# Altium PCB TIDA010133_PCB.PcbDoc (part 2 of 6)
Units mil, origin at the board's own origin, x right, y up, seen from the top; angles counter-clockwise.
Board outline 4100 x 6400 mil, 8 copper layers (Top Layer, Ground 1, Signal 1, Power 1, Ground 2, Signal 2, Power 2, Bottom Layer), stack 60.4 mil thick; 587 components, 322 nets, 1661 pads, 859 vias.
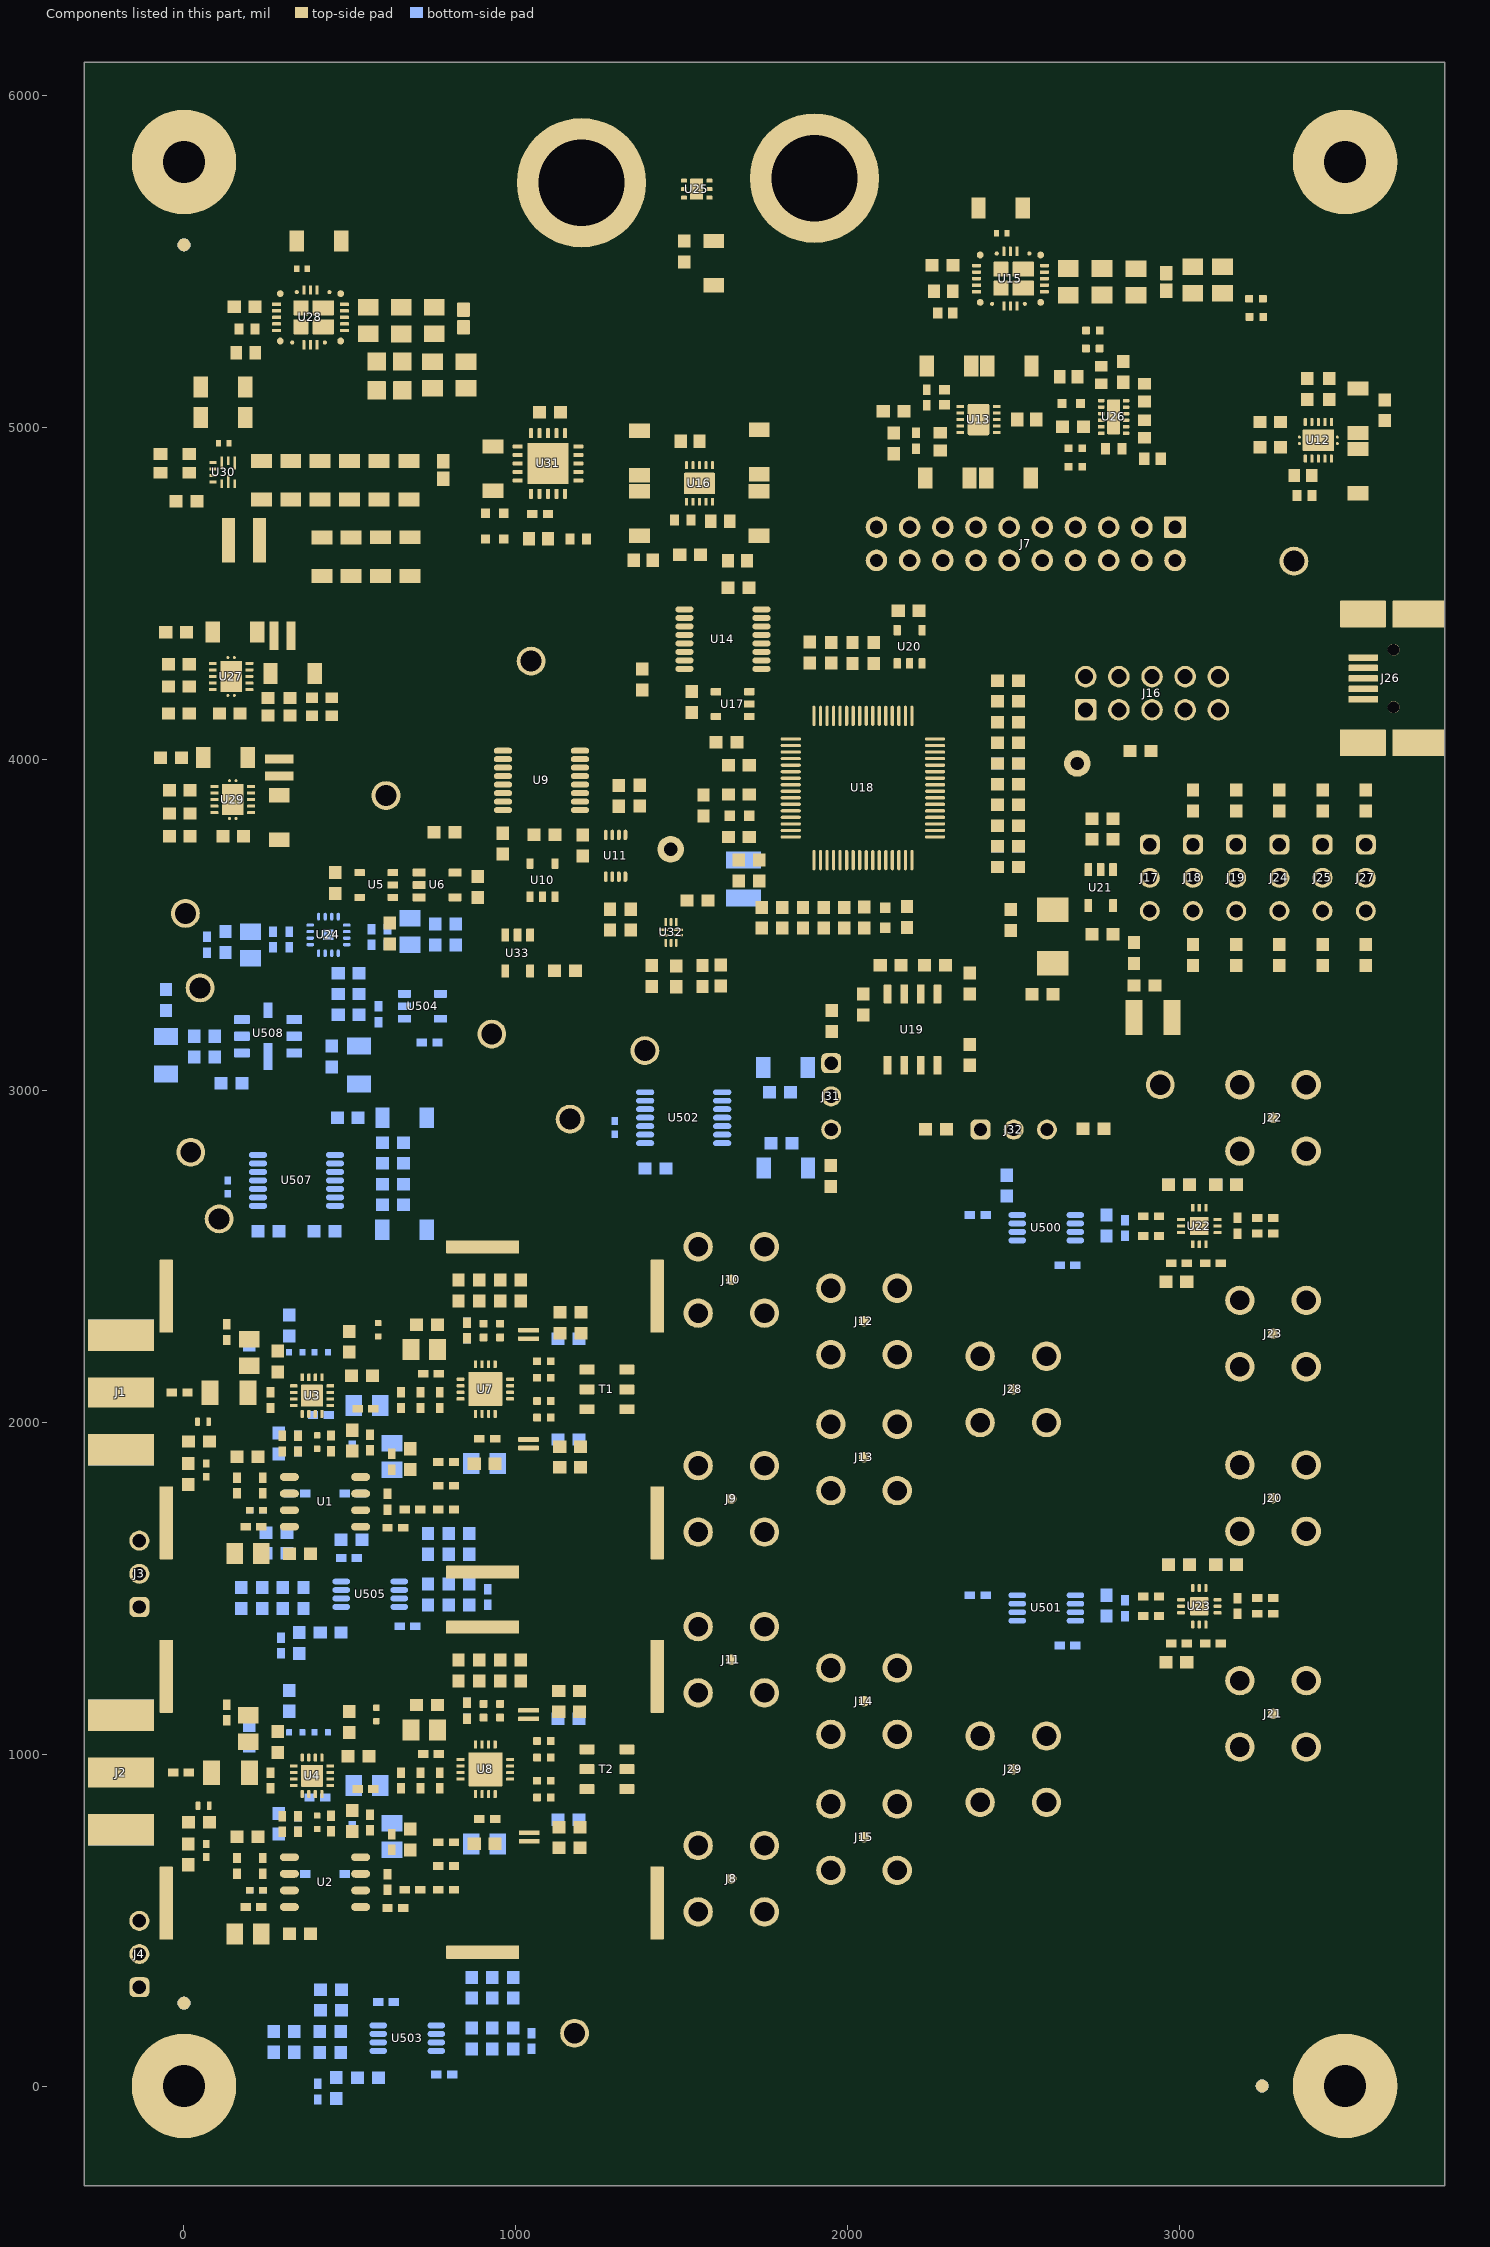
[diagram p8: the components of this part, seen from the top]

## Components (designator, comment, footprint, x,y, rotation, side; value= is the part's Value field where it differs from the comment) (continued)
U15 "TPSM82913RDUR" RDU0028A-MFG 2491.34,5448.25 r90 top locked
U16 "TPS7A3901DSCR" DSC0010J 1554,4831 r270 top locked
U17 "SN74LVC1G125DBVR" DBV0005A_L 1653.82,4165.74 r180 top locked
U18 "FT4232HL" LQFP64_L 2046.73,3912.92 r180 top locked
U19 "93LC46BT-I/SN" SOIC-8 2196.09,3184.32 r270 top locked
U20 "SN74LVC1G125DBVR" DBV0005A_L 2187.48,4338.58 r90 top locked
U21 "TLV70233DBVR" DBV0005A_N 2763.47,3612.45 r270 top locked
U22 "TLV3605RVKR" RVK0012A 3060.66,2592.43 r270 top locked
U23 "TLV3605RVKR" RVK0012A 3060.66,1446.17 r270 top locked
U24 "DAC80508MRTET" RTE0016D 435.51,3470 r90 bottom locked
U25 "TVS1400DRVR" DRV0006A 1545.46,5718.18 r180 top
U26 "LM27762DSSR" DSS0012B 2802.59,5031.38 r180 top
U27 "TPS7A9401DSC" DSC0010J-MFG 142,4249 r0 top
U28 "TPSM82913RDUR" RDU0028A-MFG 381.3,5331.75 r90 top
U29 "TPS7A9401DSC" DSC0010J-MFG 147,3878 r0 top locked
U30 "TPS62913RPUR" RPU0010A-MFG 123.51,4864.69 r90 top locked
U31 "TPS7A3301RGWR" RGW0020A 1097.32,4891.12 r90 top
U32 "TMUX121NKGR" NKG0010A-MFG 1468.15,3477.43 r0 top
U33 "SN74LVC1G126DBVR" DBV0005A_N 1005.78,3415.33 r270 top
U500 "OPA2188AIDGKT" DGK0008A_N 2599.54,2587.32 r180 bottom locked
U501 "OPA2188AIDGKT" DGK0008A_N 2599.53,1441.06 r180 bottom locked
U502 "TPL0102-100PWR" PW0014A_N 1506.25,2919.07 r0 bottom locked
U503 "OPA2188AIDGKT" DGK0008A_N 673.23,144.17 r0 bottom locked
U504 "OPA189IDBVR" DBV0005A_N 719.3,3254.91 r0 bottom locked
U505 "OPA2188AIDGKT" DGK0008A_N 561.4,1482.47 r0 bottom locked
U507 "TPL0102-100PWR" PW0014A_N 339.25,2729.91 r0 bottom locked
U508 "REF7025QFKHR" FKH0008A-MFG 253.34,3164.49 r0 bottom locked
Y1 "ABM3-12.000MHZ-D2Y-T" XTAL_ABM3 2619.41,3465.41 r90 top locked
ZZ1 "These assemblies must be clean and free from flux and all contaminants. Use of no clean flux is not acceptable." AssemblyNote -1237.69,6728.09 r0 top
ZZ2 "These assemblies must comply with workmanship standards IPC-A-610 Class 2, unless otherwise specified." AssemblyNote -1237.69,6639.53 r0 top
ZZ3 "Indication provided for the D* components at their cathode side." AssemblyNote -1237.6,6557.21 r0 top
ZZ4 "This Assembly Note is for PCB labels only" AssemblyNoteLabel -1233.49,6464.16 r0 top
ZZ5 "These assemblies are ESD sensitive, ESD precautions shall be observed." AssemblyNote -1233.49,6355.28 r0 top

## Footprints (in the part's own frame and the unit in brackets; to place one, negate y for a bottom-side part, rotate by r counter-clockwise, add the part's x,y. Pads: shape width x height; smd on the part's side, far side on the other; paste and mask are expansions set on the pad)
0306 [mm] "based on TDK recommendation (similar to Taiyo Yuden and MuRata)"
  rrect29% 0.35x1.6 smd: 1(-0.325,0) 2(0.325,0)
  body extent -0.44,-0.85 0.44,0.85, height 0.6
0402 [mm] "0402 from SM-752 data"
  rect 0.8x0.6 smd: 1(-0.6,0) 2(0.6,0)
  silkscreen extent -1.22,-0.52 1.22,0.52, body extent -0.55,-0.3 0.55,0.3, height 0.6
0402L [mm] "0402 from SM-752 data"
  rect 0.6x0.5 smd: 1(-0.5,0) 2(0.5,0)
  body extent -0.55,-0.3 0.55,0.3, height 0.6
0603 [mm] "0603 from SM-752 data"
  rect 1x0.95 smd: 1(-0.8,0) 2(0.8,0)
  silkscreen extent -1.52,-0.69 1.52,0.69, body extent -0.87,-0.47 0.87,0.47, height 1
0805_HV [mil] "0805 with 30mil clearance between pads"
  rect 50x63 smd: 1(-40,0) 2(40,0)
  silkscreen extent -74,-40 74,40, body extent -43,-29 43,29, height 57
1206 [mm] "1206 from SM-752 data"
  rect 1.3x1.85 smd: 1(-1.45,0) 2(1.45,0)
  silkscreen extent -2.4,-1.21 2.4,1.21, body extent -1.7,-0.9 1.7,0.9, height 1.35
1206_190 [mm] "1206_190"
  rect 1.1x1.6 smd: 1(-1.7,0) 2(1.7,0)
  silkscreen extent -0.9,-1 0.9,1, body extent -1.75,-0.95 1.75,0.95, height 1.9
1210_270 [mm] "1210"
  rect 1.3x2.7 smd: 1(-1.45,0) 2(1.45,0)
  silkscreen extent -2.32,-1.57 2.32,1.57, body extent -1.7,-1.35 1.7,1.35, height 2.7
AssemblyNote [mil] "Assembly Note"
AssemblyNoteLabel [mil] "Assembly Note for PCB Labels"
CAPC1608X87X35NL15T15 [mm] "Chip Capacitor, 2-Leads, Body 1.60x0.80mm, IPC Medium Density"
  rect 0.9x1 smd: 1(-0.675,0) 2(0.675,0)
  body extent -0.87,-0.48 0.87,0.47, height 0.87
CAPC1608X90X35ML10T15 [mm] "Chip Capacitor, 2-Leads, Body 1.60x0.80mm, IPC Low Density"
  rect 0.95x1.05 smd: 1(-0.725,0) 2(0.725,0)
  body extent -0.85,-0.45 0.85,0.45, height 0.9
CE_Mark_5mm [mil] "Minimum text height for CE Mark"
  silkscreen extent -138,-98 138,98
CONN_LTI_SASF546-P26-X1 [mm]
  round 0.8 smd: 1(0,0)
  round 2.25 hole 1.5: 2(-2.54,2.54) 3(-2.54,-2.54) 4(2.54,-2.54) 5(2.54,2.54)
  silkscreen extent -3.4,-3.4 3.4,3.4, body extent -3.17,-3.17 3.17,3.17, height 12.53
D0008A_N [mm] "SOIC, 8-Leads, Body 4.9x3.9mm, Pitch 1.27mm, IPC Medium Density"
  oval 1.45x0.6 smd: 1(-2.725,1.905) 2(-2.725,0.635) 3(-2.725,-0.635) 4(-2.725,-1.905) 5(2.725,-1.905) 6(2.725,-0.635) 7(2.725,0.635) 8(2.725,1.905)
  silkscreen extent -3.3,-2.5 0.9,2.5, body extent -3,-2.45 3,2.45, height 1.63
DBV0005A_L [mm] "SOT23, 5-Leads, Body 2.9x1.6mm, Pitch 0.95mm, Lead Span 2.8mm, IPC High Density"
  rrect18% 0.8x0.55 smd: 1(-1.275,0.95) 2(-1.275,0) 3(-1.275,-0.95) 4(1.275,-0.95) 5(1.275,0.95)
  silkscreen extent -0.35,-1.55 0.35,1.55, body extent -1.42,-1.46 1.42,1.46, height 1.09
DBV0005A_N [mm] "SOT23, 5-Leads, Body 2.9x1.6mm, Pitch 0.95mm, Lead Span 2.8mm, IPC Medium Density"
  rrect17% 1x0.6 smd: 1(-1.375,0.95) 2(-1.375,0) 3(-1.375,-0.95) 4(1.375,-0.95) 5(1.375,0.95)
  silkscreen extent -1.62,-1.55 0.38,1.55, body extent -1.42,-1.46 1.42,1.46, height 1.09
DCU0008A_N [mm] "TSSOP, 8-Leads, Body 2x2.3mm, Pitch 0.5mm, IPC Medium Density"
  oval 0.8x0.3 smd: 1(-1.6,0.75) 2(-1.6,0.25) 3(-1.6,-0.25) 4(-1.6,-0.75) 5(1.6,-0.75) 6(1.6,-0.25) 7(1.6,0.25) 8(1.6,0.75)
  silkscreen extent -1.05,-1.05 0.38,1.05, body extent -1.56,-1 1.56,1, height 0.9
DGK0008A_N [mm] "TSOP, 8-Leads, Body 3x3mm, Pitch 0.65mm, IPC Medium Density"
  oval 1.35x0.45 smd: 1(-2.225,0.975) 2(-2.225,0.325) 3(-2.225,-0.325) 4(-2.225,-0.975) 5(2.225,-0.975) 6(2.225,-0.325) 7(2.225,0.325) 8(2.225,0.975)
  silkscreen extent -2.75,-1.55 0.95,1.55, body extent -2.45,-1.5 2.45,1.5, height 0.96
DRV0006A [mm] "SON, 6-Leads, Body 2x2mm, Pitch 0.65mm, Thermal Pad 1.6x1mm, TI Recommended"
  rrect33% 0.45x0.3 smd: 1(-0.975,0.65) 2(-0.975,0) 3(-0.975,-0.65) 4(0.975,-0.65) 5(0.975,0) 6(0.975,0.65)
  rrect14% 1x0.7 on Top Paste: 7(0,0.45) 7(0,-0.45)
  rrect10% 1x1.6 smd paste-0.5: 7(0,0)
  silkscreen extent -1.05,-1.2 1.05,1.2, body extent -1.05,-1.05 1.05,1.05, height 0.81
DSC0010J [mm] "WSON-10"
  rrect42% 0.6x0.24 smd: 1(-1.4,1) 2(-1.4,0.5) 3(-1.4,0) 4(-1.4,-0.5) 5(-1.4,-1) 6(1.4,-1) 7(1.4,-0.5) 8(1.4,0) 9(1.4,0.5) 10(1.4,1)
  rrect12% 1.65x2.4 smd paste-1 mask-2: 11(0,0)
  Top Layer region: -0.375,-1.65 -0.375,-1.2 -0.775,-1.2 -0.794,-1.196 -0.81,-1.185 -0.821,-1.169 -0.825,-1.15 -0.825,-1.15 -0.825,1.15 -0.821,1.169 -0.81,1.185 -0.794,1.196 -0.775,1.2 -0.775,1.2 -0.375,1.2 -0.375,1.65 -0.371,1.669 -0.36,1.685 -0.344,1.696 -0.325,1.7 -0.325,1.7 -0.325,1.7 -0.175,1.7 -0.175,1.7 -0.156,1.696 -0.14,1.685 -0.129,1.669 -0.125,1.65 -0.125,1.65 -0.125,1.2 0.125,1.2 0.125,1.65 0.129,1.669 0.14,1.685 0.156,1.696 0.175,1.7 0.175,1.7 0.175,1.7 0.325,1.7 0.325,1.7 0.344,1.696 0.36,1.685 0.371,1.669 0.375,1.65 0.375,1.65 0.375,1.2 0.775,1.2 0.794,1.196 0.81,1.185 0.821,1.169 0.825,1.15 0.825,1.15 0.825,-1.15 0.821,-1.169 0.81,-1.185 0.794,-1.196 0.775,-1.2 0.775,-1.2 0.375,-1.2 0.375,-1.65 0.371,-1.669 0.36,-1.685 0.344,-1.696 0.325,-1.7 0.325,-1.7 0.175,-1.7 0.156,-1.696 0.14,-1.685 0.129,-1.669 0.125,-1.65 0.125,-1.65 0.125,-1.2 -0.125,-1.2 -0.125,-1.65 -0.129,-1.669 -0.14,-1.685 -0.156,-1.696 -0.175,-1.7 -0.175,-1.7 -0.325,-1.7 -0.344,-1.696 -0.36,-1.685 -0.371,-1.669 -0.375,-1.65
  body extent -1.5,-1.5 1.5,1.5, height 0.8
DSC0010J-MFG [mm]
  rrect42% 0.6x0.24 smd paste+0 mask+0: 1(-1.4,1) 2(-1.4,0.5) 3(-1.4,0) 4(-1.4,-0.5) 5(-1.4,-1) 6(1.4,-1) 7(1.4,-0.5) 8(1.4,0) 9(1.4,0.5) 10(1.4,1)
  round 0.225 smd paste-1000 mask+0: 11(-0.25,1.448) 11(-0.25,-1.45) 11(0.25,1.45) 11(0.25,-1.448)
  rrect6% 1.65x2.4 smd paste-1000 mask+0: 11(0,0)
  Top Layer region: 0.375,-1.2 0.375,-1.65 0.371,-1.669 0.36,-1.685 0.344,-1.696 0.325,-1.7 0.325,-1.7 0.175,-1.7 0.156,-1.696 0.14,-1.685 0.129,-1.669 0.125,-1.65 0.125,-1.65 0.125,-1.2
  Top Layer region: -0.125,-1.2 -0.125,-1.65 -0.132,-1.675 -0.15,-1.693 -0.175,-1.7 -0.175,-1.7 -0.325,-1.7 -0.344,-1.696 -0.36,-1.685 -0.371,-1.669 -0.375,-1.65 -0.375,-1.65 -0.375,-1.2
  Top Layer region: 0.125,1.2 0.125,1.65 0.129,1.669 0.14,1.685 0.156,1.696 0.175,1.7 0.175,1.7 0.325,1.7 0.344,1.696 0.36,1.685 0.371,1.669 0.375,1.65 0.375,1.65 0.375,1.2
  Top Layer region: -0.375,1.2 -0.375,1.65 -0.371,1.669 -0.36,1.685 -0.344,1.696 -0.325,1.7 -0.325,1.7 -0.175,1.7 -0.156,1.696 -0.14,1.685 -0.129,1.669 -0.125,1.65 -0.125,1.65 -0.125,1.2
  silkscreen extent -2.1,-1.55 1.55,1.55, body extent -1.8,-1.8 1.8,1.8, height 0.25
DSS0012B [mm] "WSON-10"
  rrect40% 0.5x0.25 smd: 1(-0.95,1.25) 2(-0.95,0.75) 3(-0.95,0.25) 4(-0.95,-0.25) 5(-0.95,-0.75) 6(-0.95,-1.25) 7(0.95,-1.25) 8(0.95,-0.75) 9(0.95,-0.25) 10(0.95,0.25) 11(0.95,0.75) 12(0.95,1.25)
  rrect11% 1x2.65 smd paste-0.5: 13(0,0)
  body extent -1,-1.5 1,1.5, height 0.81
Emerson_142-0701-851 [mil] "Cinch Connectivity"
  rect 90x200 smd: 1(0,-110)
  rect 95x200 smd: 2(-172.5,-110) 3(172.5,-110)
  rect 95x200 smd far side: 4(172.5,-110) 5(-172.5,-110)
  silkscreen extent -235,-220 235,0, body extent -190,-195 190,387, height 155
FCC_disclaimer [mil]
Fiducial10-20 [mm]
  round 1 smd mask+0.5: 1(0,0)
  Top Layer keep-out circle w1.178: c0,0 r0.5
FKH0008A-MFG [mm]
  rrect14% 1.2x0.7 smd: 1(-2,1.27) 2(-2,0) 3(-2,-1.27) 5(2,-1.27) 6(2,0) 7(2,1.27)
  rrect14% 0.7x1.2 smd: 4(0,-2)
  rrect14% 0.7x2.1 smd paste-1000: 8(0,1.55)
  silkscreen extent -3.09,-2.58 2.58,2.58, body extent -2.5,-2.5 2.5,2.5, height 2.14
"FP-1.0 x 1.5 x 0.25_RF_SHIELD-MFG" [mil]
  body extent -500,-750 500,750, height 250
FP-678038020_CONN_USB-MFG [mm]
  rrect20% 2.25x0.5 smd: 1(3.725,1.6) 2(3.725,0.8) 3(3.725,0) 4(3.725,-0.8) 5(3.725,-1.6)
  rrect5% 4x2.05 smd: 6(-0.5,4.925) 8(-0.5,-4.925)
  rrect5% 3.5x2.05 smd: 7(3.75,4.925) 9(3.75,-4.925)
  round 0.9 hole 0.9 unplated paste-2539.97: ""(1.4,2.2) ""(1.4,-2.2)
  Keep-Out Layer region: -2.5,-3.1 -1.3,-3.1 -1.3,3.1 -2.5,3.1
  silkscreen extent 4.62,-3.52 5.77,3.52, body extent -4.72,-6.05 5.6,6.05, height 0.25
FP-BLE18-0_15-t0_6-IPC_B [mil]
  rect 43.55x37.73 smd paste+0 mask+0: 1(-26.62,0) 2(26.62,0)
  silkscreen extent -48,-35 48,35, body extent -58,-29 58,29, height 10
FP-BLE18PS080SN1D_0603-IPC_B [mil]
  rrect10% 43.55x37.73 smd paste+0 mask+0: 1(-26.62,0) 2(26.62,0)
  silkscreen extent -48,-35 48,35, body extent -58,-29 58,29, height 10
FP-C1608-080-0_1-MFG [mm]
  rect 0.7x0.7 smd paste+0 mask+0: 1(-0.7,0) 2(0.7,0)
  silkscreen extent -0.8,-0.75 0.8,0.75, body extent -1.15,-0.55 1.15,0.55, height 0.25
FP-CRCW04020000Z0EDHP_0402-MFG [mm]
  rrect17% 0.6x0.6 smd paste+0 mask+0: 1(-0.525,0) 2(0.525,0)
  silkscreen extent -0.53,-0.7 0.53,0.7, body extent -0.92,-0.4 0.92,0.4, height 0.25
FP-ERJ-2GE0R00X_0402-MFG [mm]
  rrect21% 0.475x0.5 smd paste+0 mask+0: 1(-0.512,0) 2(0.513,0)
  silkscreen extent -0.53,-0.63 0.53,0.63, body extent -0.85,-0.38 0.85,0.38, height 0.25
FP-GRM15-MFG [mm]
  rect 0.4x0.5 smd paste+0 mask+0: 1(-0.4,0) 2(0.4,0)
  silkscreen extent -0.53,-0.63 0.53,0.63, body extent -0.7,-0.38 0.7,0.38, height 0.25
FP-GRM31C-0_2-e0_3_0_8-MFG [mm]
  rect 1.05x1.6 smd paste+0 mask+0: 1(-1.475,0) 2(1.475,0)
  silkscreen extent -0.58,-0.9 0.58,0.9, body extent -2.1,-1 2.1,1, height 0.25
FP-JR0805X35E_0805-MFG [mm]
  rrect7% 1.4x1.44 smd paste+0 mask+0: 1(-1.1,0) 2(1.1,0)
  silkscreen extent 0,-0.72 0,0.72, body extent -1.9,-0.82 1.9,0.82, height 0.25
FP-KRL2012E-M-R006-F-T5_0805-MFG [mm]
  rrect14% 0.7x2.2 smd paste+0 mask+0: 1(-0.65,0) 2(0.65,0)
  silkscreen extent -0.72,-1.5 0.72,1.5, body extent -1.1,-1.2 1.1,1.2, height 0.25
FP-WBC1-1TLB_SMT_XFRMR_3MM81_3MM81-MFG [mm]
  rrect13% 0.76x1.14 smd paste+0 mask+0: 1(-1.52,1.525) 2(0,1.525) 3(1.52,1.525) 4(1.52,-1.525) 5(0,-1.525) 6(-1.52,-1.525)
  silkscreen extent -2.09,-2.22 2.09,2.82, body extent -2.19,-2.32 2.19,2.32, height 0.25
FP-XGL4020-MFG [mm]
  rect 0.98x3.4 smd paste+0 mask+0: 1(-1.185,0) 2(1.185,0)
  silkscreen extent -2.92,-2.15 2.15,2.15, body extent -2.25,-2.25 2.25,2.25, height 0.25
Harwin_S1721-46R [mm] "RFI SHIELD CLIP TIN SMD"
  rrect10% 5.59x1.02 smd: 1(0,0)
  body extent -2.63,-0.54 2.63,0.54, height 2.23
Keystone5000 [mil] "For Keystone 500x miniature loop terminals"
  round 80 hole 40: 1(0,0)
  silkscreen extent -52,-52 52,52, body extent -49,-49 49,49, height 182
Keystone5010 [mil] "Keystone Multipurpose loops"
  round 87 hole 63: 1(0,0)
  silkscreen extent -70,-70 70,70, body extent -63,-63 63,62, height 319
Keystone5011 [mil] "Keystone Multipurpose loops"
  round 87 hole 63: 1(0,0)
  silkscreen extent -70,-70 70,70, body extent -63,-63 63,62, height 319
Keystone_1902E [mil] "Hex Standoff, 4-40 threaded, nylon"
  round 1 on Mech4: 0(0,0)
  body extent -145,-126 146,126, height 1001
Label_650x200 [mil] "Thermal Transfer Label"
  round 1 on Mech13: 0(0,0)
  silkscreen extent -325,-100 325,100, body extent -325,-100 325,100, height 1
LQFP64_L [mm] "Thin QFP, 64-Leads, Body 10x10mm, Pitch 0.5mm, IPC High Density"
  oval 1.55x0.25 smd: 1(-5.525,3.75) 2(-5.525,3.25) 3(-5.525,2.75) 4(-5.525,2.25) 5(-5.525,1.75) 6(-5.525,1.25) 7(-5.525,0.75) 8(-5.525,0.25) 9(-5.525,-0.25) 10(-5.525,-0.75) 11(-5.525,-1.25) 12(-5.525,-1.75) 13(-5.525,-2.25) 14(-5.525,-2.75) 15(-5.525,-3.25) 16(-5.525,-3.75) 33(5.525,-3.75) 34(5.525,-3.25) 35(5.525,-2.75) 36(5.525,-2.25) 37(5.525,-1.75) 38(5.525,-1.25) 39(5.525,-0.75) 40(5.525,-0.25) 41(5.525,0.25) 42(5.525,0.75) 43(5.525,1.25) 44(5.525,1.75) 45(5.525,2.25) 46(5.525,2.75) 47(5.525,3.25) 48(5.525,3.75)
  oval 0.25x1.55 smd: 17(-3.75,-5.525) 18(-3.25,-5.525) 19(-2.75,-5.525) 20(-2.25,-5.525) 21(-1.75,-5.525) 22(-1.25,-5.525) 23(-0.75,-5.525) 24(-0.25,-5.525) 25(0.25,-5.525) 26(0.75,-5.525) 27(1.25,-5.525) 28(1.75,-5.525) 29(2.25,-5.525) 30(2.75,-5.525) 31(3.25,-5.525) 32(3.75,-5.525) 49(3.75,5.525) 50(3.25,5.525) 51(2.75,5.525) 52(2.25,5.525) 53(1.75,5.525) 54(1.25,5.525) 55(0.75,5.525) 56(0.25,5.525) 57(-0.25,5.525) 58(-0.75,5.525) 59(-1.25,5.525) 60(-1.75,5.525) 61(-2.25,5.525) 62(-2.75,5.525) 63(-3.25,5.525) 64(-3.75,5.525)
  silkscreen extent -5.65,-4.35 4.35,4.55, body extent -5,-5 5,5, height 1.6
LQG15WZ_02 [mm] "MuRata recommended land pattern"
  rrect29% 0.35x0.65 smd: 1(-0.425,0) 2(0.425,0)
  body extent -0.52,-0.32 0.52,0.32, height 0.6
LTST-C191_Green [mm] "Lite-On"
  rect 0.8x0.8 smd: 1(-0.75,0) 2(0.75,0)
  silkscreen extent -1.1,-0.8 1.8,0.8, body extent -0.85,-0.45 0.85,0.45, height 0.65
Molex_0022284030 [mm] "Header, 2.54mm, 3x1, Tin, TH"
  rrect50% 1.53x1.53 hole 1.02: 1(-2.54,0)
  round 1.53 hole 1.02: 2(0,0) 3(2.54,0)
  silkscreen extent -3.81,-1.24 3.81,1.5, body extent -3.81,-1.24 3.81,1.24, height 8.38
NKG0010A-MFG [mm]
  rrect50% 0.7x0.2 smd paste+0 mask+0: 1(-0.55,0.2) 2(-0.55,-0.2) 6(0.55,-0.2) 7(0.55,0.2)
  rrect50% 0.2x0.6 smd paste+0 mask+0: 3(-0.4,-0.8) 4(0,-0.8) 5(0.4,-0.8) 8(0.4,0.8) 9(0,0.8) 10(-0.4,0.8)
  silkscreen extent -1.55,-1.12 0.92,1.12, body extent -1,-1.2 1,1.2, height 0.25
"NY PMS 440 0025 PH" [mm] "4-40 nylon screw and mounting hole"
  round 8 hole 3.2: 1(0,0)
  body extent -3.3,-3.3 3.3,3.3, height 2.69
Pomona_1581-0 [mm] "Banana Jack Black, TH"
  round 9.9 hole 6.6: 1(0,0)
  body extent -6.35,-6.35 6.35,6.35, height 7.25
Pomona_1581-2 [mm] "Banana Jack Red, TH"
  round 9.9 hole 6.6: 1(0,0)
  body extent -6.35,-6.35 6.35,6.35, height 7.25
PW0014A_N [mm] "TSOP, 14-Leads, Body 5x4.4mm, Pitch 0.65mm, IPC Medium Density"
  oval 1.4x0.45 smd: 1(-2.95,1.95) 2(-2.95,1.3) 3(-2.95,0.65) 4(-2.95,0) 5(-2.95,-0.65) 6(-2.95,-1.3) 7(-2.95,-1.95) 8(2.95,-1.95) 9(2.95,-1.3) 10(2.95,-0.65) 11(2.95,0) 12(2.95,0.65) 13(2.95,1.3) 14(2.95,1.95)
  silkscreen extent -3.4,-2.55 1.85,2.55, body extent -3.21,-2.5 3.21,2.5, height 1
PW0016A_N [mm] "TSOP, 16-Leads, Body 5x4.4mm, Pitch 0.65mm, IPC Medium Density"
  oval 1.4x0.45 smd: 1(-2.95,2.275) 2(-2.95,1.625) 3(-2.95,0.975) 4(-2.95,0.325) 5(-2.95,-0.325) 6(-2.95,-0.975) 7(-2.95,-1.625) 8(-2.95,-2.275) 9(2.95,-2.275) 10(2.95,-1.625) 11(2.95,-0.975) 12(2.95,-0.325) 13(2.95,0.325) 14(2.95,0.975) 15(2.95,1.625) 16(2.95,2.275)
  silkscreen extent -3.5,-2.55 1.85,2.75, body extent -3.21,-2.5 3.21,2.5, height 1
RDU0028A-MFG [mm]
  round 0.52 smd paste+0 mask+0: 1(-1.814,2.314) 7(-1.814,-2.314) 13(1.814,-2.314) 19(1.814,2.314)
  round 0.315 smd paste+0 mask+0: 2(-1.925,1.4) 6(-1.925,-1.1) 14(1.925,-1.45) 18(1.925,1.05)
  rrect40% 0.7x0.25 smd paste+0 mask+0: 3(-2.1,0.5) 4(-2.1,0) 5(-2.1,-0.5) 15(2.1,-0.5) 16(2.1,0) 17(2.1,0.5)
  rrect40% 0.25x0.7 smd paste+0 mask+0: 8(-1,-2.6) 9(-0.5,-2.6) 10(0,-2.6) 11(0.5,-2.6) 12(1,-2.6) 20(1,2.6) 21(0.5,2.6) 22(0,2.6) 23(-0.5,2.6) 24(-1,2.6)
  rrect9% 1.15x1.15 smd paste-1000 mask+0: 25(-0.725,0.725) 28(0.725,0.725)
  rrect9% 1.15x1.65 smd paste-1000 mask+0: 26(-0.725,-0.975) 27(0.725,-0.975)
  Top Layer region: -1.575,2.95 -1.55,2.943 -1.532,2.925 -1.525,2.9 -1.525,2.9 -1.525,2.075 -1.529,2.056 -1.54,2.04 -1.556,2.029 -1.575,2.025 -1.575,2.025 -2.4,2.025 -2.423,2.033 -2.439,2.051 -2.445,2.075 -2.445,2.075 -2.45,2.225 -2.443,2.25 -2.425,2.268 -2.4,2.275 -2.4,2.275 -2.225,2.275 -2.187,2.283 -2.154,2.304 -2.133,2.337 -2.125,2.375 -2.125,2.375 -2.125,2.575 -2.118,2.6 -2.1,2.618 -2.075,2.625 -2.075,2.625 -1.875,2.625 -1.837,2.633 -1.804,2.654 -1.783,2.687 -1.775,2.725 -1.775,2.725 -1.775,2.9 -1.768,2.925 -1.75,2.943 -1.725,2.95 -1.725,2.95
  Top Layer region: -1.575,-2.95 -1.55,-2.943 -1.532,-2.925 -1.525,-2.9 -1.525,-2.9 -1.525,-2.075 -1.529,-2.056 -1.54,-2.04 -1.556,-2.029 -1.575,-2.025 -1.575,-2.025 -2.4,-2.025 -2.423,-2.033 -2.439,-2.051 -2.445,-2.075 -2.445,-2.075 -2.45,-2.225 -2.443,-2.25 -2.425,-2.268 -2.4,-2.275 -2.4,-2.275 -2.225,-2.275 -2.187,-2.283 -2.154,-2.304 -2.133,-2.337 -2.125,-2.375 -2.125,-2.375 -2.125,-2.575 -2.118,-2.6 -2.1,-2.618 -2.075,-2.625 -2.075,-2.625 -1.875,-2.625 -1.837,-2.633 -1.804,-2.654 -1.783,-2.687 -1.775,-2.725 -1.775,-2.725 -1.775,-2.9 -1.768,-2.925 -1.75,-2.943 -1.725,-2.95 -1.725,-2.95
  Top Layer region: 1.575,-2.95 1.55,-2.943 1.532,-2.925 1.525,-2.9 1.525,-2.9 1.525,-2.075 1.529,-2.056 1.54,-2.04 1.556,-2.029 1.575,-2.025 1.575,-2.025 2.4,-2.025 2.423,-2.033 2.439,-2.051 2.445,-2.075 2.445,-2.075 2.45,-2.225 2.443,-2.25 2.425,-2.268 2.4,-2.275 2.4,-2.275 2.225,-2.275 2.187,-2.283 2.154,-2.304 2.133,-2.337 2.125,-2.375 2.125,-2.375 2.125,-2.575 2.118,-2.6 2.1,-2.618 2.075,-2.625 2.075,-2.625 1.875,-2.625 1.837,-2.633 1.804,-2.654 1.783,-2.687 1.775,-2.725 1.775,-2.725 1.775,-2.9 1.768,-2.925 1.75,-2.943 1.725,-2.95 1.725,-2.95
  Top Layer region: 1.575,2.95 1.55,2.943 1.532,2.925 1.525,2.9 1.525,2.9 1.525,2.075 1.529,2.056 1.54,2.04 1.556,2.029 1.575,2.025 1.575,2.025 2.4,2.025 2.423,2.033 2.439,2.051 2.445,2.075 2.445,2.075 2.45,2.225 2.443,2.25 2.425,2.268 2.4,2.275 2.4,2.275 2.225,2.275 2.187,2.283 2.154,2.304 2.133,2.337 2.125,2.375 2.125,2.375 2.125,2.575 2.118,2.6 2.1,2.618 2.075,2.625 2.075,2.625 1.875,2.625 1.837,2.633 1.804,2.654 1.783,2.687 1.775,2.725 1.775,2.725 1.775,2.9 1.768,2.925 1.75,2.943 1.725,2.95 1.725,2.95
  Top Layer region: -2.4,1.625 -1.8,1.625 -1.781,1.621 -1.765,1.61 -1.754,1.594 -1.75,1.575 -1.75,1.575 -1.75,0.925 -1.754,0.906 -1.765,0.89 -1.781,0.879 -1.8,0.875 -1.8,0.875 -2.4,0.875 -2.419,0.879 -2.435,0.89 -2.446,0.906 -2.45,0.925 -2.45,0.925 -2.45,1.075 -2.443,1.1 -2.425,1.118 -2.4,1.125 -2.4,1.125 -2.225,1.125 -2.187,1.133 -2.154,1.154 -2.133,1.187 -2.125,1.225 -2.125,1.225 -2.125,1.275 -2.138,1.325 -2.175,1.362 -2.225,1.375 -2.225,1.375 -2.4,1.375 -2.419,1.379 -2.435,1.39 -2.446,1.406 -2.45,1.425 -2.45,1.425 -2.45,1.575 -2.443,1.6 -2.425,1.618 -2.4,1.625
  Top Layer region: -2.4,-0.875 -1.8,-0.875 -1.775,-0.882 -1.757,-0.9 -1.75,-0.925 -1.75,-0.925 -1.75,-1.575 -1.754,-1.594 -1.765,-1.61 -1.781,-1.621 -1.8,-1.625 -1.8,-1.625 -2.4,-1.625 -2.419,-1.621 -2.435,-1.61 -2.446,-1.594 -2.45,-1.575 -2.45,-1.575 -2.45,-1.425 -2.443,-1.4 -2.425,-1.382 -2.4,-1.375 -2.4,-1.375 -2.225,-1.375 -2.187,-1.367 -2.154,-1.346 -2.133,-1.313 -2.125,-1.275 -2.125,-1.275 -2.125,-1.225 -2.138,-1.175 -2.175,-1.138 -2.225,-1.125 -2.225,-1.125 -2.4,-1.125 -2.419,-1.121 -2.435,-1.11 -2.446,-1.094 -2.45,-1.075 -2.45,-1.075 -2.45,-0.925 -2.443,-0.9 -2.425,-0.882 -2.4,-0.875
  Top Layer region: 2.4,-1.625 1.8,-1.625 1.775,-1.618 1.757,-1.6 1.75,-1.575 1.75,-1.575 1.75,-0.925 1.754,-0.906 1.765,-0.89 1.781,-0.879 1.8,-0.875 1.8,-0.875 2.4,-0.875 2.419,-0.879 2.435,-0.89 2.446,-0.906 2.45,-0.925 2.45,-0.925 2.45,-1.075 2.443,-1.1 2.425,-1.118 2.4,-1.125 2.4,-1.125 2.225,-1.125 2.187,-1.133 2.154,-1.154 2.133,-1.187 2.125,-1.225 2.125,-1.225 2.125,-1.275 2.138,-1.325 2.175,-1.362 2.225,-1.375 2.225,-1.375 2.4,-1.375 2.419,-1.379 2.435,-1.39 2.446,-1.406 2.45,-1.425 2.45,-1.425 2.45,-1.575 2.443,-1.6 2.425,-1.618 2.4,-1.625
  Top Layer region: 2.4,0.875 1.8,0.875 1.775,0.882 1.757,0.9 1.75,0.925 1.75,0.925 1.75,1.575 1.754,1.594 1.765,1.61 1.781,1.621 1.8,1.625 1.8,1.625 2.4,1.625 2.419,1.621 2.435,1.61 2.446,1.594 2.45,1.575 2.45,1.575 2.45,1.425 2.443,1.4 2.425,1.382 2.4,1.375 2.4,1.375 2.225,1.375 2.187,1.367 2.154,1.346 2.133,1.313 2.125,1.275 2.125,1.275 2.125,1.225 2.138,1.175 2.175,1.138 2.225,1.125 2.225,1.125 2.4,1.125 2.419,1.121 2.435,1.11 2.446,1.094 2.45,1.075 2.45,1.075 2.45,0.925 2.443,0.9 2.425,0.882 2.4,0.875
  silkscreen extent -3.2,-3.13 2.63,3.13, body extent -2.55,-3.05 2.55,3.05, height 0.25
RESC1608X55X30LL15T15 [mm] "Chip Resistor, 2-Leads, Body 1.60x0.80mm, IPC High Density"
  rect 0.7x0.85 smd: 1(-0.625,0) 2(0.625,0)
  body extent -0.87,-0.48 0.87,0.48, height 0.55
RESC1608X55X30ML15T15 [mm] "Chip Resistor, 2-Leads, Body 1.60x0.80mm, IPC Low Density"
  rect 0.9x1.05 smd: 1(-0.725,0) 2(0.725,0)
  body extent -0.87,-0.48 0.87,0.48, height 0.55
RESC1608X55X30NL15T15 [mm] "Chip Resistor, 2-Leads, Body 1.60x0.80mm, IPC Medium Density"
  rect 0.8x0.95 smd: 1(-0.675,0) 2(0.675,0)
  body extent -0.87,-0.48 0.87,0.48, height 0.55
RESC1609X50X30LL10T20 [mm] "Chip Resistor, 2-Leads, Body 1.55x0.85mm, IPC High Density"
  rect 0.7x0.85 smd: 1(-0.575,0) 2(0.575,0)
  body extent -0.82,-0.48 0.82,0.48, height 0.5
RESC1609X50X30ML10T20 [mm] "Chip Resistor, 2-Leads, Body 1.55x0.85mm, IPC Low Density"
  rect 0.9x1.05 smd: 1(-0.675,0) 2(0.675,0)
  body extent -0.82,-0.48 0.82,0.48, height 0.5
RESC1609X50X30NL10T20 [mm] "Chip Resistor, 2-Leads, Body 1.55x0.85mm, IPC Medium Density"
  rect 0.8x0.95 smd: 1(-0.625,0) 2(0.625,0)
  body extent -0.82,-0.48 0.82,0.48, height 0.5
RGH0016A-MFG [mm]
  rrect40% 0.6x0.25 smd: 1(-1.9,0.75) 2(-1.9,0.25) 3(-1.9,-0.25) 4(-1.9,-0.75) 9(1.9,-0.75) 10(1.9,-0.25) 11(1.9,0.25) 12(1.9,0.75)
  rrect40% 0.25x0.6 smd: 5(-0.75,-1.9) 6(-0.25,-1.9) 7(0.25,-1.9) 8(0.75,-1.9) 13(0.75,1.9) 14(0.25,1.9) 15(-0.25,1.9) 16(-0.75,1.9)
  rrect4% 2.6x2.6 smd paste-1000: 17(0,0)
  silkscreen extent -2.87,-2.05 2.05,2.05, body extent -2.3,-2.3 2.3,2.3, height 0.25
RGT0016C-MFG [mm]
  rrect42% 0.6x0.24 smd: 1(-1.4,0.75) 2(-1.4,0.25) 3(-1.4,-0.25) 4(-1.4,-0.75) 9(1.4,-0.75) 10(1.4,-0.25) 11(1.4,0.25) 12(1.4,0.75)
  rrect42% 0.24x0.6 smd: 5(-0.75,-1.4) 6(-0.25,-1.4) 7(0.25,-1.4) 8(0.75,-1.4) 13(0.75,1.4) 14(0.25,1.4) 15(-0.25,1.4) 16(-0.75,1.4)
  rrect6% 1.68x1.68 smd paste-1000: 17(0,0)
  silkscreen extent -2.31,-1.55 1.55,1.55, body extent -1.8,-1.8 1.8,1.8, height 0.25
RGW0020A [mm] "VQFN-20"
  rrect32% 0.75x0.31 smd: 1(-2.325,1.3) 2(-2.325,0.65) 3(-2.325,0) 4(-2.325,-0.65) 5(-2.325,-1.3) 11(2.325,-1.3) 12(2.325,-0.65) 13(2.325,0) 14(2.325,0.65) 15(2.325,1.3)
  rrect32% 0.31x0.75 smd: 6(-1.3,-2.325) 7(-0.65,-2.325) 8(0,-2.325) 9(0.65,-2.325) 10(1.3,-2.325) 16(1.3,2.325) 17(0.65,2.325) 18(0,2.325) 19(-0.65,2.325) 20(-1.3,2.325)
  rrect3% 3.15x3.15 smd paste-1.575: 21(0,0)
  body extent -2.5,-2.5 2.5,2.5, height 1
RPU0010A-MFG [mm]
  rrect50% 0.65x0.2 smd paste+0 mask+0: 1(-0.875,0.25) 3(-0.875,-0.75) 5(0.875,-0.25)
  rrect50% 1x0.2 smd paste+0 mask+0: 2(-0.7,-0.25) 4(0.7,-0.75) 6(0.7,0.25)
  rrect40% 0.25x0.55 smd paste+0 mask+0: 7(0.75,0.925) 8(0.25,0.925) 9(-0.25,0.925) 10(-0.75,0.925)
  silkscreen extent -1.97,-1.5 1,1.6, body extent -1.3,-1.15 1.3,1.3, height 0.25
RTE0016D [mm] "QFN, 16-Leads, Body 3x3mm, Pitch 0.5mm"
  oval 0.6x0.24 smd: 1(-1.4,0.75) 2(-1.4,0.25) 3(-1.4,-0.25) 4(-1.4,-0.75) 9(1.4,-0.75) 10(1.4,-0.25) 11(1.4,0.25) 12(1.4,0.75)
  oval 0.24x0.6 smd: 5(-0.75,-1.4) 6(-0.25,-1.4) 7(0.25,-1.4) 8(0.75,-1.4) 13(0.75,1.4) 14(0.25,1.4) 15(-0.25,1.4) 16(-0.75,1.4)
  rect 0.8x0.8 smd paste-0.85: 17(0,0)
  silkscreen extent -1.72,-1.73 1.72,1.73, body extent -1.57,-1.57 1.58,1.58, height 0.81
RVK0012A [mm] "QFN-12"
  rrect42% 0.6x0.24 smd: 1(-1.4,0.5) 2(-1.4,0) 3(-1.4,-0.5) 7(1.4,-0.5) 8(1.4,0) 9(1.4,0.5)
  rrect42% 0.24x0.6 smd: 4(-0.5,-1.4) 5(0,-1.4) 6(0.5,-1.4) 10(0.5,1.4) 11(0,1.4) 12(-0.5,1.4)
  rrect7% 1.4x1.4 smd paste-0.7: 13(0,0)
  body extent -1.58,-1.58 1.58,1.58, height 0.8
SOIC-8 [mm] "duplicate of SO-8.  SOIC, 8-Leads, Body 5.0x4.0mm (max), Pitch 1.27mm, IPC Medium Density"
  rrect17% 1.45x0.6 smd: 1(-2.725,1.905) 2(-2.725,0.635) 3(-2.725,-0.635) 4(-2.725,-1.905) 5(2.725,-1.905) 6(2.725,-0.635) 7(2.725,0.635) 8(2.725,1.905)
  silkscreen extent -3.5,-2.5 0.9,2.5, body extent -3,-2.45 3,2.45, height 1.63
TI_Stacked_Overlay_Small [mil]
  silkscreen extent -418,-98 418,98
TSW-110-07-G-D [mm] "Samtec 100mil, 2x10, 230 mil above insulator"
  rrect6% 1.65x1.65 hole 1.016: 1(-11.43,-1.27)
  round 1.65 hole 1.016: 2(-11.43,1.27) 3(-8.89,-1.27) 4(-8.89,1.27) 5(-6.35,-1.27) 6(-6.35,1.27) 7(-3.81,-1.27) 8(-3.81,1.27) 9(-1.27,-1.27) 10(-1.27,1.27) 11(1.27,-1.27) 12(1.27,1.27) 13(3.81,-1.27) 14(3.81,1.27) 15(6.35,-1.27) 16(6.35,1.27) 17(8.89,-1.27) 18(8.89,1.27) 19(11.43,-1.27) 20(11.43,1.27)
  silkscreen extent -13.73,-2.54 12.7,2.54, body extent -12.7,-2.54 12.7,2.54, height 8.38
WEEE_Minimum [mil] "WEEElie bin"
  silkscreen extent -95,-172 99,104
WURTH_61301021121 [mm] "Header, 2.54mm, 5x2, TH"
  rrect25% 1.65x1.65 hole 1.15: 1(-5.08,-1.27)
  round 1.65 hole 1.15: 2(-5.08,1.27) 3(-2.54,-1.27) 4(-2.54,1.27) 5(0,-1.27) 6(0,1.27) 7(2.54,-1.27) 8(2.54,1.27) 9(5.08,-1.27) 10(5.08,1.27)
  silkscreen extent -6.35,-2.9 6.35,2.54, body extent -6.35,-2.54 6.35,2.54, height 8.54
XTAL_ABM3 [mm] "Abracon recommended land pattern 12.28.10"
  rect 1.9x2.4 smd: 1(-2.05,0) 2(2.05,0)
  silkscreen extent -2.67,-1.78 2.67,1.78, body extent -2.6,-1.7 2.6,1.7, height 1.3

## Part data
C1 C2 C9 C10 C19 C20 C27 C28 C36 C37 C39 C40 C500 C501 C502 C503 C506 C507 C523 C526 C528 C529 C531 C532 C537 C542 C543 C546 C550 C551 C552 C555 C556 C557 C559 C560 C564 C565 C567: library part CMP-0860983-1, "CAP, CERM, 0.1 µF, 50 V,+/- 10%, X7R, 0402", Cap_Case=0402, Manufacturer="Passive Plus", TempCo=X7R, Tolerance_%=10%, Value2=50V, ValueDisplayed=0.1µF
C3 C4 C7 C8 C29 C30 C524 C525 C536 C540 C541 C544 C545 C566: library part CMP-0084177-1, "CAP, CERM, 10 µF, 25 V,+/- 10%, X5R, 0805", Cap_Case=0805, Manufacturer=Yageo, TempCo=X5R, Tolerance_%=10%, Value2=25V, ValueDisplayed=10µF
C5 C6: library part CMP-0008887-2, "CAP, CERM, 330 pF, 630 V, +/- 5%, C0G/NP0, 1206", Cap_Case=1206, Manufacturer=MuRata, Supplier Part Number 1=490-5276-1-ND, TempCo=C0G/NP0, Tolerance_%=5%, Value1=Unknown, Value2=630V, ValueDisplayed=330pF
C11 C12: library part CMP-0006478-2, "CAP, CERM, 56 pF, 50 V, +/- 5%, C0G/NP0, 0402", Cap_Case=0402, Manufacturer=MuRata, Supplier Part Number 1=14T3298, TempCo=C0G/NP0, Tolerance_%=5%, Value1=Unknown, Value2=50V, ValueDisplayed=56pF
C13 C104 C113: library part CMP-2100-03641-2, "CAP CER 0.1UF 16V X7R 0402", Capacitance=0.10μF, Manufacturer=Murata, Package=GRM15, Temperature="-55°C to +125°C", Temperature Characteristic=X7R, Temperature Range High=+125°C, Temperature Range Low=-55°C, Tolerance=10%, Voltage Rating=16V
C14 C21 C26 C35 C42 C43 C61 C68 C71 C78 C79 C105 C109 C115 C116 C123 C124 C130 C134 C136 C510 C511 C534 C535: library part CMP-0008692-2, "CAP, CERM, 10 uF, 25 V, +/- 20%, X7R, 1206_190", Cap_Case=1206, Manufacturer=TDK, Supplier Part Number 1=445-6812-1-ND, TempCo=X7R, Tolerance_%=20%, Value1=Unknown, Value2=25V, ValueDisplayed=10uF
C15 C16 C23 C24 C48 C49 C50 C51 C57 C96 C97 C98 C99 C512 C513 C530 C538 C539 C549 C568: library part CMP-0007078-4, "CAP, CERM, 0.1 uF, 50 V, +/- 10%, X7R, AEC-Q200 Grade 1, 0603", Cap_Case=0603, Manufacturer=TDK, Supplier Part Number 1=445-5666-1-ND, TempCo=X7R, Tolerance_%=10%, Value1="0.0296 ohm", Value2=50V, ValueDisplayed=0.1uF
C17 C41 C52 C54 C55 C56 C58 C64 C65 C66 C76 C81 C82 C83 C84 C85 C86 C87 C88 C89 C95: library part CMP-0006856-6, "CAP, CERM, 0.1 uF, 25 V, +/- 5%, X7R, 0603", Cap_Case=0603, Manufacturer=Kemet, Supplier Part Number 1=399-1282-1-ND, TempCo=X7R, Tolerance_%=5%, Value1=Unknown, Value2=25V, ValueDisplayed=0.1uF
C22 C114 C119 C132 C133: library part CMP-2006-03238-1, "CAP, CERM, 4.7uF, 10V, +/-10%, X5R, 0603", Manufacturer=Kemet, Voltage Rating=10V
C25 C38 C129 C547 C561: library part CMP-0006674-2, "CAP, CERM, 0.01 uF, 50 V, +/- 10%, X7R, 0402", Cap_Case=0402, Manufacturer=MuRata, Supplier Part Number 1=490-4516-1-ND, TempCo=X7R, Tolerance_%=10%, Value1=Unknown, Value2=50V, ValueDisplayed=0.01uF
C31 C32 C33 C34: library part CMP-0006231-2, "CAP, CERM, 1000 pF, 50 V, +/- 10%, X7R, 0402", Cap_Case=0402, Manufacturer="Wurth Elektronik", Supplier Part Number 1=732-7556-1-ND, TempCo=X7R, Tolerance_%=10%, Value1=Unknown, Value2=50V, ValueDisplayed=1000pF
C44 C45 C46 C47: library part CMP-0009490-2, "CAP, CERM, 0.01 uF, 25 V, +/- 20%, X7R, 0306", Cap_Case=0306, Manufacturer=MuRata, Supplier Part Number 1=490-4315-1-ND, TempCo=X7R, Tolerance_%=20%, Value1=Unknown, Value2=25V, ValueDisplayed=0.01uF
C53 C69 C77 C80: library part CMP-2006-02924-1, "CAP, 4.7nF, 50V, +/-10%, X7R, 0603", Manufacturer=Murata, Rating=50V
C70 C504 C505: library part CMP-0007318-5, "CAP, CERM, 10 uF, 10 V, +/- 20%, X5R, 0603", Cap_Case=0603, Manufacturer=MuRata, TempCo=X5R, Tolerance_%=20%, Value1=Unknown, Value2=10V, ValueDisplayed=10uF
C90 C91: library part CMP-0007249-4, "CAP, CERM, 16 pF, 100 V, +/- 5%, C0G/NP0, 0603", Cap_Case=0603, Manufacturer=MuRata, Supplier Part Number 1=490-1332-1-ND, TempCo=C0G/NP0, Tolerance_%=5%, Value1=Unknown, Value2=100V, ValueDisplayed=16pF
C92 C93 C141: library part CMP-0007037-4, "CAP, CERM, 1 uF, 16 V, +/- 10%, X7R, 0603", Cap_Case=0603, Manufacturer=TDK, Supplier Part Number 1=445-1604-1-ND, TempCo=X7R, Tolerance_%=10%, Value1="0.0057 ohm", Value2=16V, ValueDisplayed=1uF
C94 C514: library part CMP-0009206-2, "CAP, CERM, 100 uF, 10 V, +/- 20%, X5R, 1210", Cap_Case=1210, Manufacturer=MuRata, Supplier Part Number 1=490-9969-1-ND, TempCo=X5R, Tolerance_%=20%, Value1=Unknown, Value2=10V, ValueDisplayed=100uF
C100 C101 C102 C103: library part CMP-0006295-2, "CAP, CERM, 0.1 uF, 25 V, +/- 20%, X7R, 0402", Cap_Case=0402, Manufacturer=TDK, Supplier Part Number 1=445-7349-1-ND, TempCo=X7R, Tolerance_%=20%, Value1=Unknown, Value2=25V, ValueDisplayed=0.1uF
C106 C107 C108 C142 C143: library part CMP-0007826-2, "CAP, CERM, 22 uF, 16 V, +/- 10%, X5R, 0805", Cap_Case=0805, Manufacturer=TDK, Supplier Part Number 1=445-6797-1-ND, TempCo=X5R, Tolerance_%=10%, Value1=Unknown, Value2=16V, ValueDisplayed=22uF
C110 C111 C112 C145 C146: library part CMP-0860494-1, "CAP, CERM, 22 µF, 10 V,+/- 20%, X7T, 0805", Cap_Case=0805, Manufacturer=MuRata, TempCo=X7T, Tolerance_%=20%, Value2=10V, ValueDisplayed=22µF
C117 C118 C125 C126 C127 C128 C137 C138 C139 C140: library part CMP-06035-003841-1, "Chip Multilayer Ceramic Capacitors for General Purpose, 1206, 22uF, X7R, 15%, 10%, 10V", Capacitance=22uF, Case Code (Imperial)=1206, Case Code (Metric)=3216, Dielectric=X7R, Max Operating Temperature=125°C, Min Operating Temperature=-55°C, Package Quantity=1, Tolerance=10%, Voltage=10V
C120: library part CMP-08246-005464-1, "Multilayer Ceramic Capacitors 470nF ±10% 16V X5R SMD 0603", Capacitance=470nF, Case Code (Imperial)=0603, Case Code (Metric)=1608, Dielectric=X5R, Dielectric Material=Ceramic, Max Operating Temperature=85°C, Min Operating Temperature=-55°C, Package Quantity=4000, Tolerance=10%, Voltage Rating=16V
C121 C122: library part CMP-0007036-4, "CAP, CERM, 2.2 uF, 10 V, +/- 10%, X7R, 0603", Cap_Case=0603, Manufacturer=TDK, Supplier Part Number 1=445-5958-1-ND, TempCo=X7R, Tolerance_%=10%, Value1="0.004058 ohm", Value2=10V, ValueDisplayed=2.2uF
C131 C135: library part CMP-2000-04979-3, "Multilayer Ceramic Capacitors 10μF ±10% 10V X5R SMD 0603", Capacitance=10uF, Case Code (Imperial)=0603, Case Code (Metric)=1608, Dielectric=X5R, Dielectric Material=Ceramic, Max Operating Temperature=85°C, Min Operating Temperature=-55°C, Package Quantity=1, Tolerance=10%, Voltage=10V
C144 C147: library part CMP-0007389-4, "CAP, CERM, 0.22 uF, 16 V, +/- 10%, X7R, 0603", Cap_Case=0603, Manufacturer=MuRata, Supplier Part Number 1=490-3293-1-ND, TempCo=X7R, Tolerance_%=10%, Value1=Unknown, Value2=16V, ValueDisplayed=0.22uF
C527 C533 C553 C558: library part CMP-0007078-4, "CAP, CERM, 0.1 uF, 50 V, +/- 10%, X7R, AEC-Q200 Grade 1, 0603", Cap_Case=0603, Manufacturer=TDK, Supplier Part Number 1=445-5666-1-ND, TempCo=X7R, Tolerance_%=10%, Value1="0.0296 ohm", Value2=50V, ValueDisplayed="0.1uF (DNP)"
C548: library part CMP-0008821-2, "CAP, CERM, 10 uF, 35 V, +/- 10%, X7R, 1206", Cap_Case=1206, Manufacturer="Taiyo Yuden", Supplier Part Number 1=587-3007-1-ND, TempCo=X7R, Tolerance_%=10%, Value1=Unknown, Value2=35V, ValueDisplayed="10uF (DNP)"
C554: library part CMP-0006980-4, "CAP, CERM, 0.1 uF, 16 V, +/- 10%, X7R, 0603", Cap_Case=0603, Manufacturer=Kemet, Supplier Part Number 1=399-5344-1-ND, TempCo=X7R, Tolerance_%=10%, Value1=Unknown, Value2=16V, ValueDisplayed=0.1uF
C562 C563: library part CMP-0006891-4, "CAP, CERM, 2 pF, 50 V, +/- 12.5%, C0G/NP0, 0603", Cap_Case=0603, Manufacturer=Kemet, Supplier Part Number 1=399-1047-1-ND, TempCo=C0G/NP0, Tolerance_%=12.5%, Value1=Unknown, Value2=50V, ValueDisplayed=2pF
C569: library part CMP-0008821-2, "CAP, CERM, 10 uF, 35 V, +/- 10%, X7R, 1206", Cap_Case=1206, Manufacturer="Taiyo Yuden", Supplier Part Number 1=587-3007-1-ND, TempCo=X7R, Tolerance_%=10%, Value1=Unknown, Value2=35V, ValueDisplayed=10uF
D5 D6: library part CMP-0002891-3, "LED, Green, SMD", Color=green, Manufacturer=Lite-On, Value1=W, Value2=3.2V
FB1 FB2: library part CMP-0096943-2, "Ferrite Chip Bead 8A 8.5Ohm 2-Pin 0603 Paper T/R", Impedance At Frequency="8.5Ω @ 100MHz", Manufacturer=Murata, Mouser Part Number=81-BLE18PS080SN1D, Operating Temperature Range="-55°C to +125°C", Test Frequency=100MHz, Tolerance_%=25%
FB3: library part CMP-06046-000742-1, "Ferrite Chip Bead 8A 8.5Ohm 2-Pin 0603 Paper T/R", Manufacturer=Murata
FID1 FID2 FID3 FID4 FID5 FID6: library part CMP-0077181-1, "Fiducial mark.  There is nothing to buy or mount.", Manufacturer=N/A
H1 H2 H15 H16: library part CMP-0003617-1, "Machine Screw, Round, #4-40 x 1/4, Nylon, Philips panhead", Manufacturer="B&F Fastener Supply", Supplier Part Number 1=H542-ND
H3 H4 H5 H6 H7 H8 H9 H10 H11 H12 H13 H14: library part CMP-0086134-1, "RFI SHIELD CLIP TIN SMD", Manufacturer=Harwin
H500 H501 H502 H503: library part CMP-0003611-1, "Standoff, Hex, 1\"L #4-40 Nylon", Manufacturer=Keystone, Supplier Part Number 1=36-1902E-ND
J1 J2: library part CMP-0055822-3, "Connector, End launch SMA, 50 ohm, SMT", Manufacturer="Cinch Connectivity", Supplier Part Number 1=J658-ND
J3 J4 J17 J18 J19 J24 J25 J27 J31 J32: library part CMP-0078237-1, "Header, 2.54mm, 3x1, Tin, TH", Color=Black, Current_A=4A, Manufacturer=Molex, Supplier Part Number 1=WM50014-03-ND, Voltage_V=500V
J5: library part CMP-0082515-1, "Banana Jack Red, TH", Color=Red, Current_A=15A, Manufacturer="Pomona Electronics", Supplier Part Number 1=501-1080-ND
J7: library part CMP-0075421-2, "Header, 100mil, 10x2, Gold, TH", Color=Black, Current_A=6.3A, Manufacturer=Samtec, Supplier Part Number 1=SAM1028-10-ND, Voltage_V=550V
J8 J9 J10 J11 J12 J13 J14 J15 J20 J21 J22 J23 J28 J29: library part CMP-0055826-1, "Connector, SMA,Vertical, Thru hole w/SMT center pin", Manufacturer="Lighthorse Technologies"
J16: library part CMP-0054806-3, "Header, 2.54 mm, 5x2, Gold, TH", Current_A=3A, Manufacturer="Wurth Elektronik", Supplier Part Number 1=732-2672-ND, Voltage_V=250V
J26: library part CMP-0088148-1, "MOLEX 67803-8020 MINI USB, 2.0 OTG TYPE AB, RCPT, TH", Current_A=1A, Manufacturer=Molex, Voltage_V=30V
J30: library part CMP-0082516-1, "Banana Jack Black, TH", Color=Black, Current_A=15A, Manufacturer="Pomona Electronics", Supplier Part Number 1=501-1078-ND
L1 L2: library part CMP-0080319-3, "Inductor, Multilayer, Air Core, 6.8 nH, 0.7 A, 0.14 ohm, AEC-Q200 Grade 1, SMD", Manufacturer=MuRata, Supplier Part Number 1=490-15294-1-ND, Value1="0.14 ohm", Value2=0.7A, ValueDisplayed=6.8nH
L3 L4 L7 L8 L9 L10 L11 L12 L13 L14 L500 L501 L502 L503 L504 L509 L510 L511 L512 L513 L514 L515 L516: library part CMP-0003352-2, "Ferrite Bead, 120 ohm @ 100 MHz, 3 A, 0603", Manufacturer=MuRata, Supplier Part Number 1=490-3996-1-ND, Value1="0.025 ohm", Value2=3A, ValueDisplayed="120 ohm"
L16: library part CMP-11268-000045-2, "Shielded Power Inductors"
L20 L21 L22: library part CMP-0003354-2, "Ferrite Bead, 26 ohm @ 100 MHz, 6 A, 0603", Manufacturer=MuRata, Supplier Part Number 1=490-3995-1-ND, Value1="0.007 ohm", Value2=6A, ValueDisplayed="26 ohm"
LBL1: library part CMP-0003625-1, "Thermal Transfer Printable Labels, 0.650\" W x 0.200\" H - 10,000 per roll", Manufacturer=Brady, Supplier Part Number 1=97C5133
Logo1: library part CMP-0074844-2, Manufacturer="Texas Instruments"
Logo2: library part CMP-0074847-1, "FCC_disclaimer"
Logo3: library part CMP-0074769-4, Manufacturer="Texas Instruments"
Logo4: library part CMP-0074838-1, "Texas Instrument Corporate Signature"
MP1 MP2: library part CMP-0096146-1, "Standard RF Shield 1.0 x 1.5 x 0.25", Manufacturer=Fotofab, Operating Temperature Range=to
R1 R2: library part CMP-0023033-5, "RES, 330, 1%, 0.1 W, 0603", Manufacturer=Yageo, Power_W=100mW, Supplier Part Number 1=311-330HRCT-ND, TempCo="100 ppm/C", Tolerance_%=1%, Value2=0.1W, Value_Code=330R, ValueDisplayed=330
R3 R4: library part CMP-0023387-3, "RES, 50, 0.1%, 0.125 W, 0603", Manufacturer="Vishay Thin Film", Power_W=125mW, Supplier Part Number 1=FC0603-50BFCT-ND, TempCo="25 ppm/C", Tolerance_%=0.1%, Value2=0.125W, Value_Code=50R0, ValueDisplayed=50
R5 R6: library part CMP-0026904-3, "RES, 30, 5%, 0.063 W, AEC-Q200 Grade 0, 0402", Manufacturer=Vishay-Dale, Power_W=63mW, Supplier Part Number 1=541-30JCT-ND, TempCo="200 ppm/C", Tolerance_%=5%, Value2=0.063W, Value_Code=30R0, ValueDisplayed=30
R7 R8: library part CMP-0026003-3, "RES, 13.0 k, 1%, 0.063 W, AEC-Q200 Grade 0, 0402", Manufacturer=Vishay-Dale, Power_W=63mW, Supplier Part Number 1=541-13.0KLCT-ND, TempCo="100 ppm/C", Tolerance_%=1%, Value2=0.063W, Value_Code=13k0, ValueDisplayed=13.0k
R9 R10 R81 R107 R115 R126 R127 R128 R129 R130 R132 R141 R142 R147 R148 R533 R556: library part CMP-0025697-4, "RES, 0, 5%, 0.1 W, AEC-Q200 Grade 0, 0603", Manufacturer=Vishay-Dale, Power_W=100mW, Supplier Part Number 1=541-0.0GCT-ND, TempCo="200 ppm/C", Tolerance_%=5%, Value2=0.1W, Value_Code=0000, ValueDisplayed=0
R11 R12: library part CMP-0026162-2, "RES, 20.0 k, 1%, 0.063 W, AEC-Q200 Grade 0, 0402", Manufacturer=Vishay-Dale, Power_W=63mW, Supplier Part Number 1=541-20.0KLCT-ND, TempCo="100 ppm/C", Tolerance_%=1%, Value2=0.063W, Value_Code=20k0, ValueDisplayed=20.0k
R13 R14: library part CMP-0026549-2, "RES, 787 k, 1%, 0.063 W, AEC-Q200 Grade 0, 0402", Manufacturer=Vishay-Dale, Power_W=63mW, Supplier Part Number 1=541-787KLCT-ND, TempCo="100 ppm/C", Tolerance_%=1%, Value2=0.063W, Value_Code=787k
R15 R16: library part CMP-0025962-3, "RES, 10.0 M, 1%, 0.063 W, AEC-Q200 Grade 0, 0402", Manufacturer=Vishay-Dale, Power_W=63mW, Supplier Part Number 1=541-10.0MLCT-ND, TempCo="100 ppm/C", Tolerance_%=1%, Value2=0.063W, Value_Code=10M0, ValueDisplayed=10.0M
R17 R18: library part CMP-0026676-1, "RES, 2.00 k, 1%, 0.1 W, AEC-Q200 Grade 0, 0402", Manufacturer=Panasonic, Power_W=100mW, Supplier Part Number 1=P2.00KLCT-ND, TempCo="100 ppm/C", Tolerance_%=1%, Value2=0.1W, Value_Code=2k00, ValueDisplayed=2.00k
R19 R20 R180 R181 R536 R537 R543 R544: library part CMP-0002710-1, "0 Ohms Jumper Chip Resistor 0402 (1005 Metric) Automotive AEC-Q200 Thick Film", Digikey Part Number=P0.0JCT-ND, Manufacturer=Panasonic, Mouser Part Number=667-ERJ-2GE0R00X, Operating Temperature Range="-55°C to +155°C", Power=100mW
R21 R22: library part CMP-0026051-3, "RES, 17.8 k, 1%, 0.063 W, AEC-Q200 Grade 0, 0402", Manufacturer=Vishay-Dale, Power_W=63mW, Supplier Part Number 1=541-17.8KLCT-ND, TempCo="100 ppm/C", Tolerance_%=1%, Value2=0.063W, Value_Code=17k8, ValueDisplayed=17.8k
R23 R28 R29 R50 R55 R63 R64 R65 R66 R67 R68 R69 R70 R71 R76 R85 R93 R94 R95 R96 R97 R102 R104 R105 R106 R109 R111 R112 R131 R135 R136 R151 R152 R156 R157 R161 R162 R163 R164 R165 R166 R168 R170 R172 R173 R174 R176 R502 R503 R504 R505 R527 R528: library part CMP-0025701-4, "RES, 10 k, 5%, 0.1 W, AEC-Q200 Grade 0, 0603", Manufacturer=Vishay-Dale, Power_W=100mW, Supplier Part Number 1=541-10KGCT-ND, TempCo="200 ppm/C", Tolerance_%=5%, Value2=0.1W, Value_Code=10k0, ValueDisplayed=10k
R24 R25 R545 R546: library part CMP-0025899-5, "RES, 1.0 k, 5%, 0.1 W, 0603", Manufacturer=Yageo, Power_W=100mW, Supplier Part Number 1=311-1.0KGRCT-ND, TempCo="100 ppm/C", Tolerance_%=5%, Value2=0.1W, Value_Code=1k00, ValueDisplayed=1.0k
R26 R27 R530 R531: library part CMP-0026551-2, "RES, 78.7 k, 1%, 0.063 W, AEC-Q200 Grade 0, 0402", Manufacturer=Vishay-Dale, Power_W=63mW, Supplier Part Number 1=541-78.7KLCT-ND, TempCo="100 ppm/C", Tolerance_%=1%, Value2=0.063W, Value_Code=78k7, ValueDisplayed=78.7k
R30 R31 R539 R540: library part CMP-0026082-3, "RES, 1.30 k, 1%, 0.063 W, AEC-Q200 Grade 0, 0402", Manufacturer=Vishay-Dale, Power_W=63mW, Supplier Part Number 1=541-1.30KLCT-ND, TempCo="100 ppm/C", Tolerance_%=1%, Value2=0.063W, Value_Code=1k30, ValueDisplayed=1.30k
R32 R33 R34 R35 R38 R39: library part CMP-0026401-2, "RES, 499 k, 1%, 0.063 W, AEC-Q200 Grade 0, 0402", Manufacturer=Vishay-Dale, Power_W=63mW, Supplier Part Number 1=541-499KLCT-ND, TempCo="100 ppm/C", Tolerance_%=1%, Value2=0.063W, Value_Code=499k
R36 R37 R158 R159: library part CMP-0025951-3, "RES, 100, 1%, 0.063 W, AEC-Q200 Grade 0, 0402", Manufacturer=Vishay-Dale, Power_W=63mW, Supplier Part Number 1=541-100LCT-ND, TempCo="100 ppm/C", Tolerance_%=1%, Value2=0.063W, Value_Code=100R, ValueDisplayed=100
R40 R41 R46 R47: library part CMP-0026030-3, "RES, 15.0, 1%, 0.063 W, AEC-Q200 Grade 0, 0402", Manufacturer=Vishay-Dale, Power_W=63mW, Supplier Part Number 1=541-15.0LCT-ND, TempCo="100 ppm/C", Tolerance_%=1%, Value2=0.063W, Value_Code=15R0, ValueDisplayed=15.0
R42 R43 R44 R45: library part CMP-0026159-2, "RES, 200, 1%, 0.063 W, AEC-Q200 Grade 0, 0402", Manufacturer=Vishay-Dale, Power_W=63mW, Supplier Part Number 1=541-200LCT-ND, TempCo="100 ppm/C", Tolerance_%=1%, Value2=0.063W, Value_Code=200R, ValueDisplayed=200
R48 R49 R60 R61: library part CMP-0022590-4, "RES, 75.0, 1%, 0.1 W, AEC-Q200 Grade 0, 0603", Manufacturer=Vishay-Dale, Power_W=100mW, Supplier Part Number 1=541-75.0HCT-ND, TempCo="100 ppm/C", Tolerance_%=1%, Value2=0.1W, Value_Code=75R0, ValueDisplayed=75.0
R51 R52 R56 R57: library part CMP-0022227-5, "RES, 237, 1%, 0.1 W, AEC-Q200 Grade 0, 0603", Manufacturer=Vishay-Dale, Power_W=100mW, Supplier Part Number 1=541-237HCT-ND, TempCo="100 ppm/C", Tolerance_%=1%, Value2=0.1W, Value_Code=237R, ValueDisplayed=237
R53 R54 R58 R59 R78 R79 R86 R88 R92 R100 R118 R119 R120 R121 R122 R123 R124 R125: library part CMP-0001606-2, "RES Thick Film, 0Ω, 0.2W, 0402", Digikey Part Number=541-0.0YBCT-ND, Manufacturer="Vishay Dale", Mouser Part Number=71-CRCW04020000Z0EDH, Operating Temperature Range="-55°C to +155°C", Power_W=200mW
R62: library part CMP-0022200-4, "RES, 200 k, 1%, 0.1 W, AEC-Q200 Grade 0, 0603", Manufacturer=Vishay-Dale, Power_W=100mW, Supplier Part Number 1=541-200KHCT-ND, TempCo="100 ppm/C", Tolerance_%=1%, Value2=0.1W, Value_Code=200k
R72 R73 R74 R75: library part CMP-0023087-5, "RES, 3.74 k, 1%, 0.1 W, 0603", Manufacturer=Yageo, Power_W=100mW, Supplier Part Number 1=311-3.74KHRCT-ND, TempCo="100 ppm/C", Tolerance_%=1%, Value2=0.1W, Value_Code=3k74, ValueDisplayed=3.74k
R77: library part CMP-2000-03094-1, "RES 22.1K, 1%, 0.1W, 0603", Manufacturer="Vishay Dale"
R80: library part CMP-2000-02924-1, "RES 15.4K, 1%, 0.1W, 0603", Manufacturer="Vishay Dale"
R82 R171 R178: library part CMP-2000-00532-1, "RES, 4.87k, 1%, 0.1W, 0603", Manufacturer=Panasonic
R83: library part CMP-2000-03860-1, "RES 11k, 1%, 0.1W, 0603", Manufacturer="Vishay Dale"
R87: library part CMP-2000-03080-1, "RES 21k, 1%, 0.1W, 0603", Manufacturer="Vishay Dale"
R90: library part CMP-2000-00656-1, "RES 82k, 1%, 0.1W, 0603", Manufacturer=Panasonic
R91: library part CMP-2000-03571-1, "RES 75k, 1%, 0.1W, 0603", Manufacturer="Vishay Dale"
R98: library part CMP-2000-03445-1, "51.1 kOhms ±1% 0.1W, 1/10W Chip Resistor 0603 (1608 Metric) Automotive AEC-Q200 Thick Film", Manufacturer="Vishay Dale"
R99: library part CMP-2000-00556-1, "53.6 kOhms ±1% 0.1W, 1/10W Chip Resistor 0603 (1608 Metric) Automotive AEC-Q200 Thick Film", Manufacturer=Panasonic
